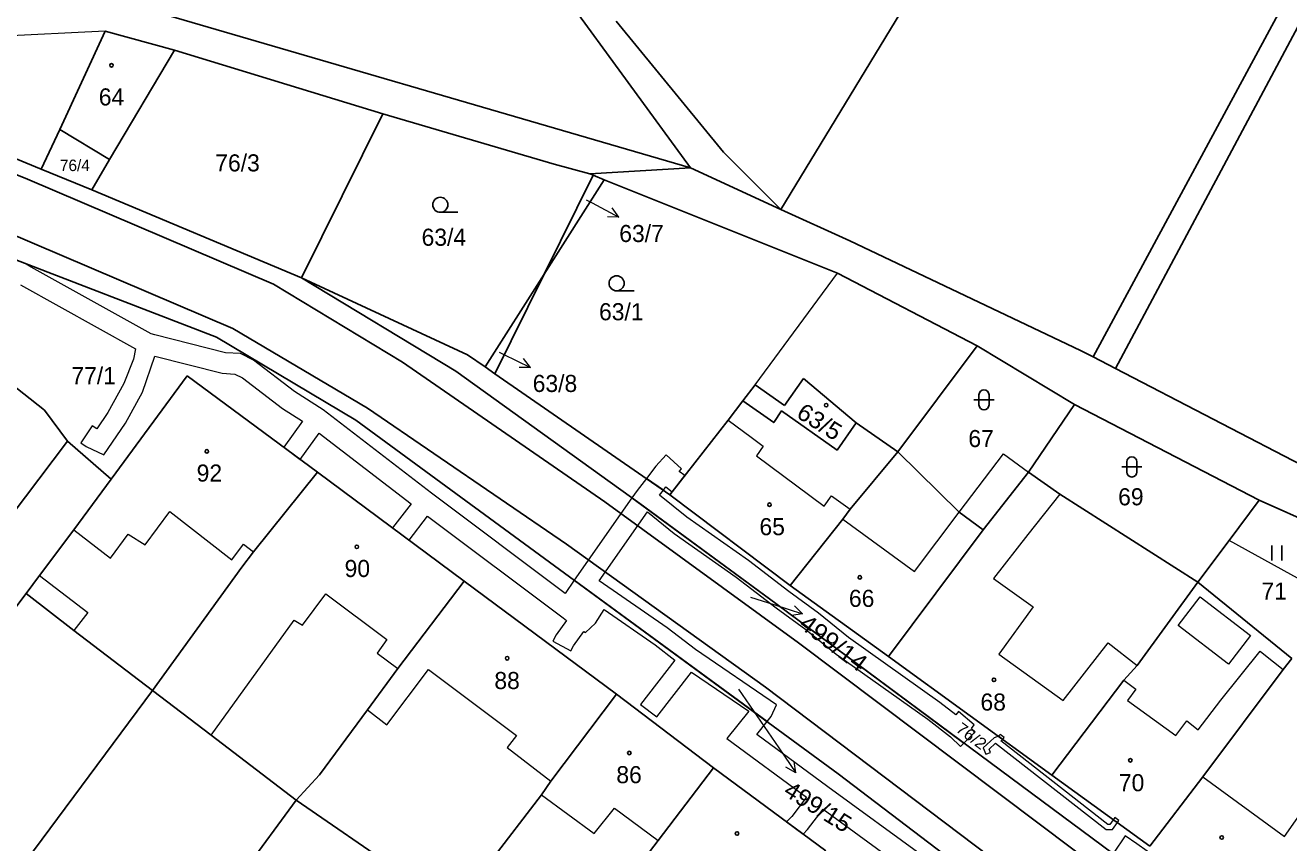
# Model space of a CAD drawing. Extents: x -606517 to -602431, y -1183120 to -1179397.
# Drawn here: x -605244.5 to -605119, y -1181091.7 to -1181010.4 of the extents above; entities that cross this region are included whole.
import ezdxf
from ezdxf.enums import TextEntityAlignment as Align

# ---------------------------------------------------------------- set-up
doc = ezdxf.new("R2010")
doc.units = 0
doc.header["$LTSCALE"] = 0.68
for name, color, linetype, lineweight in [('1', 7, 'Continuous', 25), ('13', 7, 'Continuous', 13), ('3', 7, 'Continuous', 25), ('4', 7, 'Continuous', 13), ('5', 7, 'Continuous', 25), ('7', 7, 'Continuous', 13)]:
    doc.layers.add(name, color=color, linetype=linetype, lineweight=lineweight)
doc.layers.add('2', color=7, linetype='Continuous')

msp = doc.modelspace()

# ---------------------------------------------------------------- linework, layer by layer
at = {"layer": '1'}
for p, q in [((-605078.46, -1180932.14), (-605138.39, -1181043.38)), ((-605076.15, -1180931.95), (-605136.19, -1181044.52)), ((-605128.32, -1180960.97), (-605169.43, -1181028.73)), ((-605211.73, -1180978.74), (-605178.4, -1181024.58)), ((-605235.88, -1181007.77), (-605178.4, -1181024.58)), ((-605236.55, -1181010.99), (-605241.08, -1181020.76)), ((-605229.68, -1181012.89), (-605236.55, -1181010.99)), ((-605175.11, -1181023.02), (-605185.78, -1181010.01)), ((-605236.13, -1181023.76), (-605229.68, -1181012.89)), ((-605208.98, -1181019.2), (-605229.68, -1181012.89)), ((-605265.59, -1181015.49), (-605242.91, -1181024.7)), ((-605244.28, -1181025.71), (-605264.02, -1181017.75)), ((-605217.05, -1181035.51), (-605208.98, -1181019.2)), ((-605208.98, -1181019.2), (-605191.94, -1181024.21)), ((-605242.91, -1181024.7), (-605241.08, -1181020.76)), ((-605241.08, -1181020.76), (-605236.13, -1181023.76)), ((-605236.13, -1181023.76), (-605237.87, -1181026.75)), ((-605169.43, -1181028.73), (-605175.11, -1181023.02)), ((-605269.85, -1181024.33), (-605225.51, -1181041.42)), ((-605242.91, -1181024.7), (-605237.87, -1181026.75)), ((-605191.94, -1181024.21), (-605188.4, -1181025.19)), ((-605178.4, -1181024.58), (-605188.4, -1181025.19)), ((-605169.43, -1181028.73), (-605178.4, -1181024.58)), ((-605244.28, -1181025.71), (-605219.82, -1181036.16)), ((-605188.08, -1181025.32), (-605192.95, -1181035.16)), ((-605192.95, -1181035.16), (-605186.98, -1181025.76)), ((-605186.98, -1181025.76), (-605163.8, -1181035.04)), ((-605237.87, -1181026.75), (-605217.05, -1181035.51)), ((-605162.57, -1181031.85), (-605169.43, -1181028.73)), ((-605223.86, -1181040.55), (-605246.54, -1181030.86)), ((-605139.64, -1181042.73), (-605162.57, -1181031.85)), ((-605163.8, -1181035.04), (-605149.91, -1181042.29)), ((-605219.82, -1181036.16), (-605207.03, -1181043.91)), ((-605217.05, -1181035.51), (-605201.72, -1181044.78)), ((-605217.05, -1181035.51), (-605200.55, -1181043.17)), ((-605198.8, -1181044.38), (-605192.95, -1181035.16)), ((-605192.95, -1181035.16), (-605197.84, -1181045.05)), ((-605210.51, -1181048.47), (-605223.86, -1181040.55)), ((-605225.51, -1181041.42), (-605211.65, -1181049.67)), ((-605157.81, -1181052.8), (-605149.91, -1181042.29)), ((-605149.91, -1181042.29), (-605140.26, -1181048.12)), ((-605248.85, -1181043.75), (-605242.6, -1181048.68)), ((-605200.55, -1181043.17), (-605198.8, -1181044.38)), ((-605138.39, -1181043.38), (-605139.64, -1181042.73)), ((-605138.39, -1181043.38), (-605136.19, -1181044.52)), ((-605207.03, -1181043.91), (-605186.92, -1181057.78)), ((-605201.72, -1181044.78), (-605183.44, -1181057.95)), ((-605198.8, -1181044.38), (-605197.84, -1181045.05)), ((-605197.84, -1181045.05), (-605180.45, -1181057.09)), ((-605136.19, -1181044.52), (-605116.76, -1181054.62)), ((-605228.4, -1181045.27), (-605235.95, -1181055.52)), ((-605215.47, -1181054.84), (-605228.4, -1181045.27)), ((-605173.21, -1181047.76), (-605171.98, -1181046.17)), ((-605171.98, -1181046.17), (-605169.06, -1181048.21)), ((-605169.06, -1181048.21), (-605167.18, -1181045.53)), ((-605167.18, -1181045.53), (-605161.93, -1181049.92)), ((-605242.6, -1181048.68), (-605240.31, -1181051.74)), ((-605210.51, -1181048.47), (-605190.71, -1181061.98)), ((-605174.67, -1181049.66), (-605173.21, -1181047.76)), ((-605144.81, -1181054.83), (-605140.26, -1181048.12)), ((-605140.26, -1181048.12), (-605121.89, -1181057.63)), ((-605163.73, -1181084.82), (-605211.65, -1181049.67)), ((-605180.45, -1181057.09), (-605174.67, -1181049.66)), ((-605161.93, -1181049.92), (-605157.81, -1181052.8)), ((-605240.31, -1181051.74), (-605248.45, -1181062.54)), ((-605240.31, -1181051.74), (-605235.95, -1181055.52)), ((-605162.55, -1181058.52), (-605157.81, -1181052.8)), ((-605157.81, -1181052.8), (-605151.72, -1181058.8)), ((-605215.47, -1181054.84), (-605221.82, -1181062.77)), ((-605200.89, -1181065.66), (-605215.47, -1181054.84)), ((-605149.33, -1181060.58), (-605144.81, -1181054.83)), ((-605144.81, -1181054.83), (-605141.72, -1181057.04)), ((-605235.95, -1181055.52), (-605239.67, -1181060.57)), ((-605168.51, -1181066.11), (-605180.45, -1181057.09)), ((-605141.72, -1181057.04), (-605128, -1181065.78)), ((-605124.89, -1181061.63), (-605121.89, -1181057.63)), ((-605121.89, -1181057.63), (-605111.06, -1181062.46)), ((-605186.92, -1181057.78), (-605167.67, -1181071.82)), ((-605183.44, -1181057.95), (-605169.93, -1181067.9)), ((-605163.28, -1181059.51), (-605162.55, -1181058.52)), ((-605151.72, -1181058.8), (-605149.33, -1181060.58)), ((-605168.51, -1181066.11), (-605163.28, -1181059.51)), ((-605239.67, -1181060.57), (-605243.08, -1181065.12)), ((-605158.72, -1181073.15), (-605149.33, -1181060.58)), ((-605170.96, -1181076.23), (-605190.71, -1181061.98)), ((-605128, -1181065.78), (-605124.89, -1181061.63)), ((-605221.82, -1181062.77), (-605222.98, -1181064.28)), ((-605243.08, -1181065.12), (-605244.41, -1181066.91)), ((-605222.98, -1181064.28), (-605231.85, -1181076.56)), ((-605207.49, -1181074.35), (-605200.89, -1181065.66)), ((-605185.74, -1181076.9), (-605200.89, -1181065.66)), ((-605168.51, -1181066.11), (-605158.72, -1181073.15)), ((-605134.02, -1181074.05), (-605128, -1181065.78)), ((-605128, -1181065.78), (-605118.66, -1181073.37)), ((-605244.41, -1181066.91), (-605252.17, -1181077.14)), ((-605239.66, -1181070.57), (-605244.41, -1181066.91)), ((-605169.93, -1181067.9), (-605134.38, -1181094.27)), ((-605231.85, -1181076.56), (-605239.66, -1181070.57)), ((-605167.67, -1181071.82), (-605143.76, -1181089.79)), ((-605158.72, -1181073.15), (-605142.5, -1181084.97)), ((-605119.53, -1181074.46), (-605118.66, -1181073.37)), ((-605210.51, -1181078.46), (-605207.49, -1181074.35)), ((-605135.36, -1181075.51), (-605134.02, -1181074.05)), ((-605127.48, -1181085.14), (-605119.53, -1181074.46)), ((-605147.22, -1181094.13), (-605170.96, -1181076.23)), ((-605142.5, -1181084.97), (-605135.36, -1181075.51)), ((-605231.85, -1181076.56), (-605265.64, -1181122.03)), ((-605226.04, -1181081), (-605231.85, -1181076.56)), ((-605185.74, -1181076.9), (-605192.28, -1181085.55)), ((-605176.13, -1181084.23), (-605185.74, -1181076.9)), ((-605215.26, -1181084.92), (-605210.51, -1181078.46)), ((-605217.59, -1181087.45), (-605226.04, -1181081)), ((-605217.59, -1181087.45), (-605215.26, -1181084.92)), ((-605181.62, -1181091.47), (-605176.13, -1181084.23)), ((-605164.97, -1181092.49), (-605176.13, -1181084.23)), ((-605124.28, -1181114.86), (-605163.73, -1181084.82)), ((-605142.5, -1181084.97), (-605132.75, -1181092.02)), ((-605132.75, -1181092.02), (-605127.48, -1181085.14)), ((-605192.28, -1181085.55), (-605193.22, -1181086.91)), ((-605251.63, -1181133.76), (-605217.59, -1181087.45)), ((-605201.94, -1181098.18), (-605217.59, -1181087.45)), ((-605193.22, -1181086.91), (-605198.33, -1181093.61)), ((-605143.76, -1181089.79), (-605131.39, -1181099.08)), ((-605184.76, -1181095.58), (-605181.62, -1181091.47))]:
    msp.add_line(p, q, dxfattribs=at)
for points in [[(-605188.4, -1181025.19), (-605188.08, -1181025.32), (-605186.98, -1181025.76)], [(-605173.21, -1181047.76), (-605170.13, -1181049.9), (-605169.35, -1181048.75), (-605163.84, -1181052.64), (-605161.93, -1181049.92)]]:
    msp.add_lwpolyline(points, dxfattribs=at)
at = {"layer": '13'}
for points in [[(-605155.13, -1181093.16), (-605164.77, -1181086.12), (-605171.82, -1181080.93), (-605170.79, -1181079.64), (-605189.95, -1181065.59), (-605190.86, -1181066.89), (-605204.12, -1181056.94), (-605214.91, -1181048.63), (-605217.75, -1181046.8), (-605221.82, -1181043.71), (-605223.13, -1181043.04), (-605224.61, -1181042.96), (-605231.61, -1181041.19), (-605231.98, -1181041.07), (-605243.93, -1181034.46), (-605244.59, -1181034.07)], [(-605244.99, -1181036.22), (-605233.54, -1181042.56), (-605233.75, -1181043.61), (-605234.71, -1181046.02), (-605236.28, -1181048.92), (-605237.38, -1181050.52), (-605237.85, -1181050.23), (-605238.97, -1181051.93), (-605238.44, -1181052.28), (-605236.68, -1181053.1), (-605234.54, -1181049.98), (-605232.85, -1181046.88), (-605231.61, -1181043.31), (-605224.93, -1181045), (-605223.69, -1181045.08), (-605222.92, -1181045.47), (-605218.93, -1181048.5), (-605216.96, -1181049.77), (-605218.82, -1181052.36), (-605217.18, -1181053.57), (-605215.3, -1181050.95), (-605206.16, -1181057.98), (-605208.01, -1181060.38), (-605206.37, -1181061.6), (-605204.53, -1181059.21), (-605191.07, -1181069.31), (-605190.71, -1181069.58), (-605191.75, -1181071), (-605192.09, -1181071.63), (-605190.29, -1181072.59), (-605190.03, -1181072.1), (-605189, -1181070.69), (-605188.82, -1181070.79), (-605187.83, -1181069.86), (-605186.97, -1181068.5), (-605181.92, -1181072.01), (-605179.96, -1181073.52), (-605183.36, -1181077.94), (-605181.74, -1181079.18), (-605178.3, -1181074.71), (-605172.59, -1181078.6), (-605174.78, -1181081.31), (-605166.87, -1181087.14), (-605168.33, -1181089.06), (-605168.85, -1181089.62), (-605167.21, -1181090.84), (-605166.77, -1181090.38), (-605165.22, -1181088.34), (-605156.33, -1181094.84)]]:
    msp.add_lwpolyline(points, dxfattribs=at)
for points in [[(-605182.79, -1181055.47), (-605181.1, -1181056.64), (-605180.85, -1181056.31), (-605180.22, -1181056.79), (-605178.97, -1181055.18), (-605179.53, -1181054.76), (-605179.3, -1181054.5), (-605180.82, -1181053.12), (-605181.83, -1181054.23)], [(-605182.79, -1181055.47), (-605183.71, -1181056.65), (-605184.22, -1181057.39), (-605169.93, -1181067.9), (-605151.23, -1181081.77), (-605150.13, -1181080.67), (-605150.49, -1181080.31), (-605150.21, -1181079.97), (-605151.77, -1181078.65), (-605152.03, -1181078.96), (-605153.63, -1181077.73), (-605162.69, -1181071.28), (-605165.67, -1181068.86), (-605168.64, -1181066.7), (-605172.65, -1181063.61), (-605178.76, -1181059.3), (-605181.47, -1181057.11), (-605181.1, -1181056.64)], [(-605170.79, -1181079.64), (-605170.38, -1181079.14), (-605169.86, -1181077.96), (-605177.92, -1181072.48), (-605180.72, -1181070.33), (-605187.47, -1181065.64), (-605182.69, -1181058.78), (-605180.02, -1181060.94), (-605173.87, -1181065.27), (-605169.88, -1181068.34), (-605166.93, -1181070.48), (-605163.93, -1181072.92), (-605154.83, -1181079.41), (-605152.57, -1181081.15), (-605151.59, -1181082.13), (-605151.23, -1181081.77), (-605169.93, -1181067.9), (-605183.44, -1181057.95), (-605184.22, -1181057.39), (-605189.95, -1181065.59)], [(-605135.98, -1181089.68), (-605136.39, -1181089.39), (-605136.74, -1181089.87), (-605136.92, -1181089.86), (-605147.58, -1181081.55), (-605147.37, -1181081.42), (-605147.81, -1181081.1), (-605148.23, -1181081.24), (-605149.32, -1181082.25), (-605149.06, -1181082.89), (-605148.6, -1181082.71), (-605148.72, -1181082.39), (-605148.09, -1181081.79), (-605137.1, -1181090.36), (-605136.48, -1181090.37)], [(-605147.81, -1181081.1), (-605147.37, -1181081.42), (-605147.22, -1181081.22), (-605147.62, -1181080.93)], [(-605136.39, -1181089.39), (-605135.98, -1181089.68), (-605135.84, -1181089.48), (-605136.24, -1181089.19)], [(-605135.22, -1181091.01), (-605136.38, -1181092.71), (-605135.2, -1181093.52), (-605129.83, -1181097.32), (-605129.93, -1181097.45), (-605128.26, -1181098.65), (-605127.17, -1181097.31), (-605127.91, -1181096.16), (-605134.06, -1181091.8)]]:
    msp.add_lwpolyline(points, close=True, dxfattribs=at)
at = {"layer": '3'}
for p, q in [((-605203.263, -1181029), (-605201.513, -1181029)), ((-605185.743, -1181036.81), (-605183.993, -1181036.81)), ((-605150.241, -1181047.651), (-605148.239, -1181047.651)), ((-605149.741, -1181047.151), (-605149.741, -1181048.152)), ((-605148.739, -1181048.152), (-605148.739, -1181047.151)), ((-605135.051, -1181053.821), (-605135.051, -1181054.822)), ((-605134.049, -1181054.822), (-605134.049, -1181053.821)), ((-605135.551, -1181054.321), (-605133.549, -1181054.321)), ((-605120.631, -1181063.63), (-605120.631, -1181062.13)), ((-605119.63, -1181063.63), (-605119.63, -1181062.13))]:
    msp.add_line(p, q, dxfattribs=at)
for centre in [(-605203.2629, -1181028.2498), (-605185.7429, -1181036.0598)]:
    msp.add_circle(centre, 0.75, dxfattribs=at)
for centre, start, end in [((-605149.24, -1181047.1509), 0, 180), ((-605149.24, -1181048.1509), 180, 359.98789), ((-605134.55, -1181053.8209), 0, 180), ((-605134.55, -1181054.8209), 180, 359.98789)]:
    msp.add_arc(centre, 0.5, start, end, dxfattribs=at)
at = {"layer": '4'}
for p, q in [((-605236.55, -1181010.99), (-605267.44, -1181012.5)), ((-605171.98, -1181046.17), (-605163.8, -1181035.04)), ((-605174.67, -1181049.66), (-605172.39, -1181051.36)), ((-605172.39, -1181051.36), (-605171.19, -1181052.26)), ((-605171.19, -1181052.26), (-605171.83, -1181053.22)), ((-605171.83, -1181053.22), (-605165.13, -1181058.22)), ((-605151.72, -1181058.8), (-605147.3, -1181053.03)), ((-605147.3, -1181053.03), (-605144.81, -1181054.83)), ((-605165.13, -1181058.22), (-605164.4, -1181057.19)), ((-605164.4, -1181057.19), (-605162.55, -1181058.52)), ((-605141.72, -1181057.04), (-605144.88, -1181061.05)), ((-605232.6, -1181062.06), (-605230.14, -1181058.76)), ((-605230.14, -1181058.76), (-605223.99, -1181063.54)), ((-605156.13, -1181064.71), (-605151.72, -1181058.8)), ((-605163.28, -1181059.51), (-605156.13, -1181064.71)), ((-605239.67, -1181060.57), (-605236.03, -1181063.4)), ((-605236.03, -1181063.4), (-605234.26, -1181061)), ((-605234.26, -1181061), (-605232.6, -1181062.06)), ((-605144.88, -1181061.05), (-605148.31, -1181065.42)), ((-605223.99, -1181063.54), (-605222.8, -1181062.01)), ((-605222.8, -1181062.01), (-605221.82, -1181062.77)), ((-605114.49, -1181067.38), (-605124.89, -1181061.63)), ((-605243.08, -1181065.12), (-605238.29, -1181068.78)), ((-605148.31, -1181065.42), (-605144.35, -1181068.23)), ((-605216.95, -1181070.04), (-605214.63, -1181066.92)), ((-605214.63, -1181066.92), (-605208.56, -1181071.48)), ((-605129.95, -1181070.07), (-605127.75, -1181067.22)), ((-605127.75, -1181067.22), (-605122.76, -1181071.07)), ((-605238.29, -1181068.78), (-605239.66, -1181070.57)), ((-605144.35, -1181068.23), (-605147.76, -1181072.94)), ((-605226.04, -1181081), (-605217.79, -1181069.55)), ((-605217.79, -1181069.55), (-605216.95, -1181070.04)), ((-605124.95, -1181073.92), (-605129.95, -1181070.07)), ((-605208.56, -1181071.48), (-605209.54, -1181072.85)), ((-605122.76, -1181071.07), (-605124.95, -1181073.92)), ((-605141.36, -1181077.53), (-605136.91, -1181071.81)), ((-605136.91, -1181071.81), (-605134.02, -1181074.05)), ((-605125.72, -1181077.5), (-605121.79, -1181072.63)), ((-605121.79, -1181072.63), (-605121.43, -1181072.92)), ((-605209.54, -1181072.85), (-605207.49, -1181074.35)), ((-605147.76, -1181072.94), (-605141.36, -1181077.53)), ((-605121.43, -1181072.92), (-605119.53, -1181074.46)), ((-605208.56, -1181079.97), (-605204.45, -1181074.47)), ((-605204.45, -1181074.47), (-605195.7, -1181081.02)), ((-605135.36, -1181075.51), (-605134.14, -1181076.41)), ((-605134.14, -1181076.41), (-605134.97, -1181077.53)), ((-605134.97, -1181077.53), (-605130.19, -1181081.02)), ((-605127.96, -1181080.46), (-605125.72, -1181077.5)), ((-605210.51, -1181078.46), (-605208.56, -1181079.97)), ((-605130.19, -1181081.02), (-605129.1, -1181079.55)), ((-605129.1, -1181079.55), (-605127.96, -1181080.46)), ((-605195.7, -1181081.02), (-605196.61, -1181082.23)), ((-605196.61, -1181082.23), (-605192.28, -1181085.55)), ((-605127.48, -1181085.14), (-605119.39, -1181091.07)), ((-605193.22, -1181086.91), (-605187.99, -1181090.76)), ((-605187.99, -1181090.76), (-605185.96, -1181088.23)), ((-605185.96, -1181088.23), (-605181.62, -1181091.47)), ((-605119.39, -1181091.07), (-605117.21, -1181087.96))]:
    msp.add_line(p, q, dxfattribs=at)
at = {"layer": '5'}
for centre in [(-605235.9368, -1181014.3792), (-605164.9168, -1181048.1692), (-605226.4568, -1181052.7692), (-605170.5568, -1181058.0692), (-605211.5568, -1181062.2592), (-605161.5768, -1181065.2992), (-605196.6168, -1181073.3392), (-605148.2468, -1181075.4792), (-605184.4868, -1181082.7592), (-605134.6968, -1181083.4892), (-605173.7768, -1181090.7592), (-605125.6168, -1181091.1592)]:
    msp.add_circle(centre, 0.175, dxfattribs=at)
at = {"layer": '7'}
for p, q in [((-605185.52, -1181029.469), (-605186.169, -1181028.557)), ((-605194.313, -1181044.426), (-605194.993, -1181043.536)), ((-605167.276, -1181068.927), (-605168.074, -1181068.142)), ((-605167.942, -1181084.728), (-605168.087, -1181083.618))]:
    msp.add_line(p, q, dxfattribs=at)
for points in [[(-605188.77, -1181027.75), (-605188.17, -1181028.06), (-605185.52, -1181029.469), (-605186.64, -1181029.441)], [(-605197.41, -1181042.92), (-605197.01, -1181043.11), (-605194.313, -1181044.426), (-605195.432, -1181044.437)], [(-605172.44, -1181067.26), (-605170.13, -1181068), (-605167.276, -1181068.927), (-605168.383, -1181069.094)], [(-605173.64, -1181076.4), (-605169.62, -1181082.24), (-605167.942, -1181084.728), (-605168.917, -1181084.178)]]:
    msp.add_lwpolyline(points, dxfattribs=at)

# ---------------------------------------------------------------- texts
at = {"layer": '2'}
for s, height, p in [('64', 1.7, (-605235.929, -1181018.375)), ('76/4', 1.14, (-605239.57, -1181024.9)), ('76/3', 1.7, (-605223.409, -1181024.935)), ('63/4', 1.7, (-605202.909, -1181032.325)), ('63/7', 1.7, (-605183.269, -1181031.955)), ('77/1', 1.7, (-605237.709, -1181046.095)), ('63/8', 1.7, (-605191.869, -1181046.865)), ('67', 1.7, (-605149.529, -1181052.345))]:
    msp.add_text(s, height=height, dxfattribs=at).set_placement(p, align=Align.CENTER)
for s, p in [('63/1', (-605187.49, -1181039.735)), ('92', (-605227.47, -1181055.775)), ('69', (-605135.91, -1181058.135)), ('65', (-605171.55, -1181061.105)), ('90', (-605212.77, -1181065.265)), ('71', (-605121.68, -1181067.515)), ('66', (-605162.66, -1181068.235)), ('88', (-605197.89, -1181076.405)), ('68', (-605149.59, -1181078.545)), ('86', (-605185.77, -1181085.765)), ('70', (-605135.84, -1181086.565))]:
    msp.add_text(s, height=1.7, dxfattribs=at).set_placement(p)
for s, height, rotation, width, p in [('63/5', 1.7, 328, 1.05, (-605166.0249, -1181050.5433)), ('76/2', 1.139, 323, 1.1, (-605150.8262, -1181081.5279))]:
    msp.add_text(s, height=height, rotation=rotation, dxfattribs=dict(at, width=width)).set_placement(p, align=Align.CENTER)
for s, rotation, width, p in [('499/14', 323, 1.1, (-605167.753, -1181070.188)), ('499/15', 328, 1.05, (-605169.279, -1181086.885))]:
    msp.add_text(s, height=1.7, rotation=rotation, dxfattribs=dict(at, width=width)).set_placement(p)

doc.saveas('drawing.dxf')
